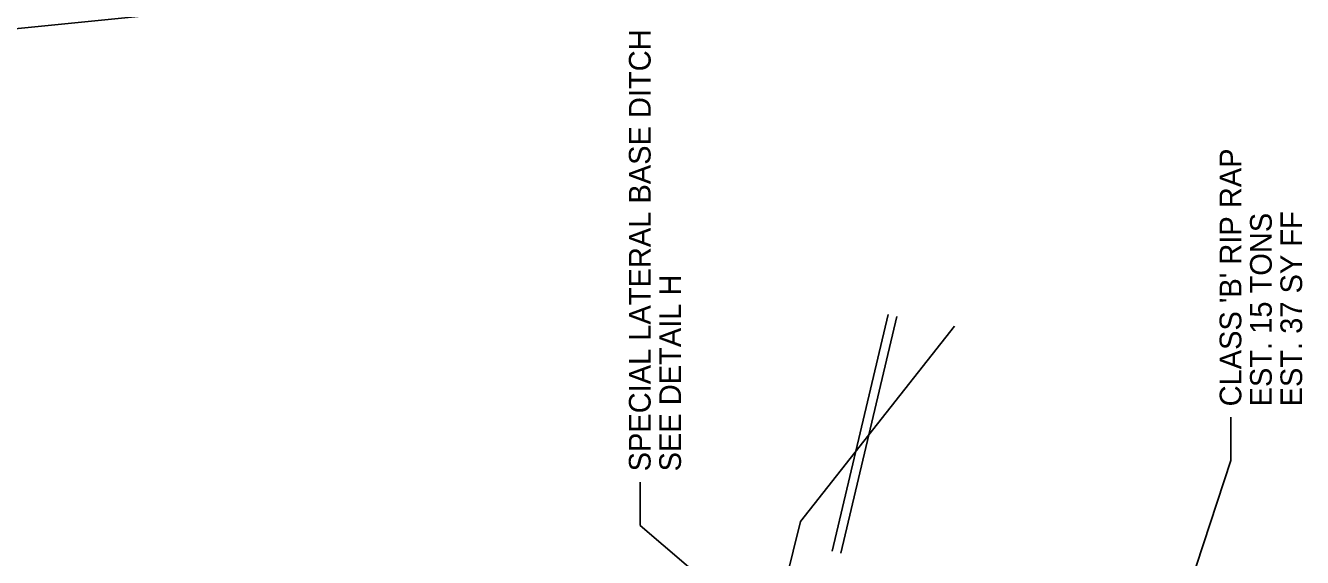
# Model space of a CAD drawing. Extents: x 2384780 to 2405432, y 547869 to 573706.
# Drawn here: x 2397627.6 to 2397921.7, y 554737.6 to 554860.1 of the extents above; entities that cross this region are included whole.
import ezdxf

# ---------------------------------------------------------------- set-up
doc = ezdxf.new("R2010")
doc.units = 0
for name, color, linetype in [('Old_Level_5', 7, 'Continuous'), ('Old_Level_63', 7, 'Continuous'), ('Prop Earthen Structure Ditch Flow Line', 7, 'Continuous'), ('Prop Earthen Structure Ditch Label', 7, 'Continuous'), ('Prop Erosion Rip Rap Class B Label', 7, 'Continuous')]:
    doc.layers.add(name, color=color, linetype=linetype)

msp = doc.modelspace()

# ---------------------------------------------------------------- linework, layer by layer
at = {"layer": 'Old_Level_5'}
msp.add_line((2397806.09, 554745.82), (2397841.57, 554790.86), dxfattribs=at)
msp.add_lwpolyline([(2397777.3, 554622.87), (2397782.04, 554648.66), (2397806.09, 554745.82)], dxfattribs=at)
at = {"layer": 'Old_Level_63'}
msp.add_lwpolyline([(2395727.98, 554147.46), (2397412.66, 554838.04), (2397895.8, 554886.52)], dxfattribs=at)
at = {"layer": 'Prop Earthen Structure Ditch Flow Line'}
for p, q in [((2397826.31, 554793.5), (2397813.41, 554739.03)), ((2397828.25, 554793.04), (2397815.35, 554738.57))]:
    msp.add_line(p, q, dxfattribs=at)
at = {"layer": 'Prop Earthen Structure Ditch Label'}
for p in [(2397769.12, 554754.88), (2397806.68, 554712.93)]:
    msp.add_line(p, (2397769.12, 554744.88), dxfattribs=at)
at = {"layer": 'Prop Erosion Rip Rap Class B Label'}
for p in [(2397905.19, 554769.85), (2397892.76, 554722.12)]:
    msp.add_line(p, (2397905.19, 554759.85), dxfattribs=at)

# ---------------------------------------------------------------- texts
at = {"layer": 'Prop Earthen Structure Ditch Label'}
for s, p in [('SPECIAL LATERAL BASE DITCH', (2397771.56, 554757.38)), ('SEE DETAIL H', (2397778.56, 554757.38))]:
    msp.add_text(s, height=5, rotation=90, dxfattribs=at).set_placement(p)
at = {"layer": 'Prop Erosion Rip Rap Class B Label'}
for s, p in [("CLASS 'B' RIP RAP", (2397907.63, 554772.35)), ('EST. 15 TONS', (2397914.63, 554772.35)), ('EST. 37 SY FF', (2397921.63, 554772.35))]:
    msp.add_text(s, height=5, rotation=90, dxfattribs=at).set_placement(p)

doc.saveas('drawing.dxf')
